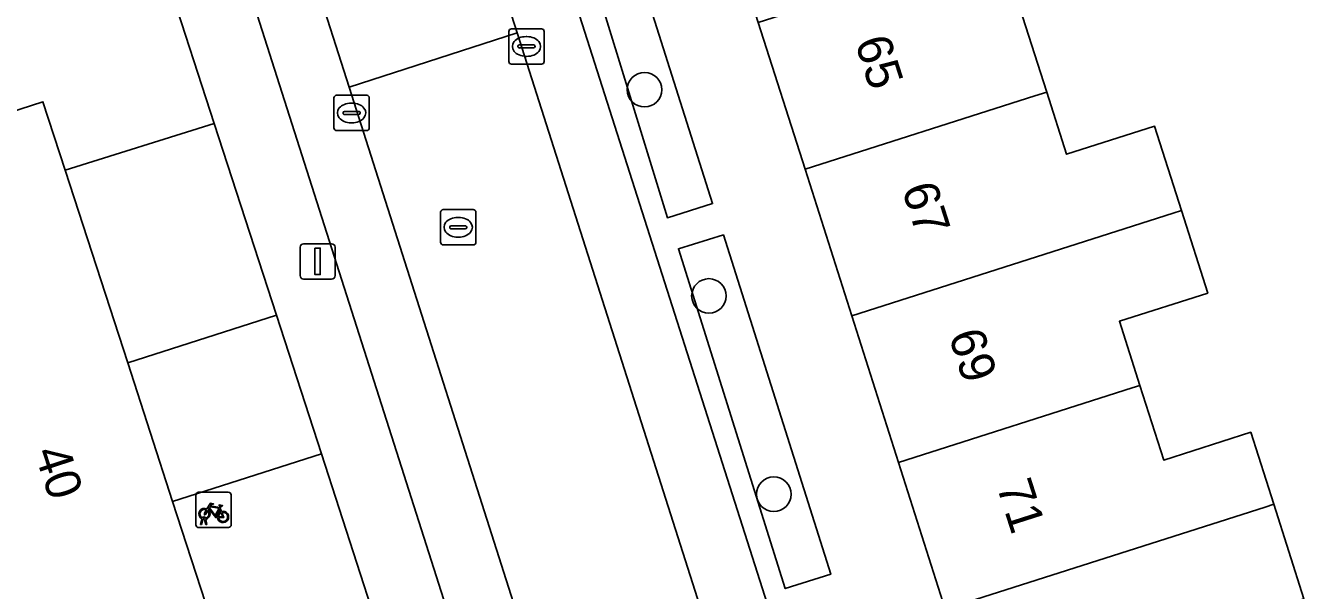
# Model space of a CAD drawing. Extents: x 159716 to 160783, y 383290 to 384031.
# Drawn here: x 160170.4 to 160206.79, y 383519.22 to 383535.21 of the extents above; entities that cross this region are included whole.
import ezdxf

# ---------------------------------------------------------------- set-up
doc = ezdxf.new("R2010")
doc.units = 0
for name, color, linetype in [('IMGEO_Boom', 7, 'Continuous'), ('IMGEO_Erf', 7, 'Continuous'), ('IMGEO_Fietsenrek', 7, 'Continuous'), ('IMGEO_Groenvoorziening', 7, 'Continuous'), ('IMGEO_Kolk', 7, 'Continuous'), ('IMGEO_Lichtmast', 7, 'Continuous'), ('IMGEO_Pand', 7, 'Continuous'), ('IMGEO_Pand_nummerreeks', 7, 'Continuous'), ('IMGEO_Parkeervlak_open', 7, 'Continuous'), ('IMGEO_Rijbaan_lokaal_open', 7, 'Continuous'), ('IMGEO_Rioolput', 7, 'Continuous'), ('IMGEO_Voetpad_open', 7, 'Continuous')]:
    doc.layers.add(name, color=color, linetype=linetype)

msp = doc.modelspace()

# ---------------------------------------------------------------- linework, layer by layer
at = {"layer": 'IMGEO_Boom'}
for centre in [(160187.928, 383533.395), (160189.752, 383527.554), (160191.59, 383521.938)]:
    msp.add_circle(centre, 0.489, dxfattribs=at)
at = {"layer": 'IMGEO_Erf'}
msp.add_lwpolyline([(160198.635, 383535.471), (160199.32, 383533.328), (160199.883, 383531.565), (160202.374, 383532.36), (160203.137, 383529.971), (160203.883, 383527.636), (160201.381, 383526.837), (160201.961, 383525.019), (160202.636, 383522.906), (160205.101, 383523.693), (160205.752, 383521.653), (160206.607, 383518.975)], dxfattribs=at)
at = {"layer": 'IMGEO_Fietsenrek'}
for p, q in [((160175.222, 383521.069), (160175.222, 383521.91)), ((160175.222, 383521.91), (160175.222, 383521.069)), ((160175.297, 383521.994), (160176.138, 383521.994)), ((160176.138, 383521.994), (160175.297, 383521.994)), ((160176.222, 383521.919), (160176.222, 383521.078)), ((160176.222, 383521.078), (160176.222, 383521.919)), ((160175.909, 383521.543), (160175.945, 383521.448)), ((160175.349, 383521.078), (160175.388, 383521.238)), ((160175.418, 383521.226), (160175.383, 383521.078)), ((160175.46, 383521.25), (160175.459, 383521.254)), ((160175.501, 383521.078), (160175.467, 383521.22)), ((160175.491, 383521.261), (160175.492, 383521.254)), ((160175.499, 383521.224), (160175.534, 383521.078)), ((160176.147, 383520.994), (160175.306, 383520.994)), ((160175.306, 383520.994), (160176.147, 383520.994)), ((160175.383, 383521.078), (160175.349, 383521.078)), ((160175.534, 383521.078), (160175.501, 383521.078))]:
    msp.add_line(p, q, dxfattribs=at)
for points in [[(160175.535, 383521.52), (160175.63, 383521.684), (160175.716, 383521.67), (160175.718, 383521.661), (160175.662, 383521.65), (160175.635, 383521.605), (160175.891, 383521.564)], [(160175.878, 383521.539), (160175.621, 383521.58), (160175.604, 383521.551), (160175.771, 383521.331), (160175.878, 383521.539)], [(160175.891, 383521.564), (160175.916, 383521.613), (160175.91, 383521.617), (160175.887, 383521.621), (160175.875, 383521.628), (160175.874, 383521.631), (160175.876, 383521.636), (160175.971, 383521.621), (160175.973, 383521.611), (160175.963, 383521.598), (160175.951, 383521.592), (160175.937, 383521.598), (160175.909, 383521.543)], [(160175.556, 383521.468), (160175.504, 383521.378), (160175.464, 383521.353), (160175.465, 383521.4), (160175.52, 383521.494)], [(160175.831, 383521.276), (160175.781, 383521.276), (160175.59, 383521.527), (160175.571, 383521.495)], [(160175.926, 383521.441), (160175.896, 383521.518), (160175.787, 383521.3), (160175.83, 383521.3)], [(160175.86, 383521.3), (160175.98, 383521.299), (160175.936, 383521.413)], [(160175.956, 383521.42), (160176.011, 383521.275), (160175.861, 383521.275)]]:
    msp.add_lwpolyline(points, dxfattribs=at)
for centre, radius, start, end in [((160175.3, 383521.916), 0.0779, 92.4484, 184.2845), ((160175.3, 383521.916), 0.0779, 92.4484, 184.2845), ((160176.144, 383521.916), 0.0779, 2.4484, 94.2845), ((160176.144, 383521.916), 0.0779, 2.4484, 94.2845), ((160175.462, 383521.379), 0.159, 62.6766, 242.1369), ((160175.462, 383521.379), 0.129, 63.3192, 238.903), ((160175.442, 383521.25), 0.0499, 12.8025, 158.6934), ((160175.462, 383521.379), 0.159, 253.9967, 271.7867), ((160175.442, 383521.25), 0.0174, 12.8025, 163.4502), ((160175.462, 383521.379), 0.129, 253.415, 269.0204), ((160175.462, 383521.379), 0.129, 283.6043, 43.4302), ((160175.462, 383521.379), 0.159, 283.5766, 46.6042), ((160175.989, 383521.295), 0.159, 113.3408, 178.3217), ((160175.989, 383521.295), 0.159, 187.0065, 105.7708), ((160175.989, 383521.295), 0.129, 113.923, 177.9556), ((160175.989, 383521.295), 0.129, 188.6715, 104.5883), ((160175.3, 383521.072), 0.0779, 182.4484, 274.2845), ((160175.3, 383521.072), 0.0779, 182.4484, 274.2845), ((160176.144, 383521.072), 0.0779, 272.4484, 4.2845), ((160176.144, 383521.072), 0.0779, 272.4484, 4.2845)]:
    msp.add_arc(centre, radius, start, end, dxfattribs=at)
at = {"layer": 'IMGEO_Groenvoorziening'}
for points in [[(160186.825, 383539.745), (160185.621, 383539.378), (160188.578, 383529.766), (160189.857, 383530.17)], [(160190.164, 383529.282), (160188.887, 383528.888), (160191.916, 383519.265), (160193.203, 383519.673)]]:
    msp.add_lwpolyline(points, close=True, dxfattribs=at)
at = {"layer": 'IMGEO_Kolk'}
for p, q in [((160184.084, 383534.193), (160184.084, 383535.045)), ((160184.159, 383535.119), (160185.011, 383535.119)), ((160185.085, 383535.045), (160185.085, 383534.193)), ((160184.386, 383534.662), (160184.784, 383534.662)), ((160184.572, 383534.899), (160184.597, 383534.899)), ((160184.343, 383534.613), (160184.343, 383534.625)), ((160184.781, 383534.576), (160184.383, 383534.576)), ((160184.595, 383534.339), (160184.57, 383534.339)), ((160184.827, 383534.625), (160184.827, 383534.613)), ((160185.011, 383534.119), (160184.159, 383534.119)), ((160179.206, 383533.237), (160180.058, 383533.237)), ((160179.131, 383532.311), (160179.131, 383533.163)), ((160179.619, 383533.017), (160179.644, 383533.017)), ((160180.132, 383533.163), (160180.132, 383532.311)), ((160179.39, 383532.731), (160179.39, 383532.743)), ((160179.828, 383532.694), (160179.43, 383532.694)), ((160179.433, 383532.78), (160179.831, 383532.78)), ((160179.642, 383532.457), (160179.617, 383532.457)), ((160179.874, 383532.743), (160179.874, 383532.731)), ((160180.058, 383532.237), (160179.206, 383532.237))]:
    msp.add_line(p, q, dxfattribs=at)
for points in [[(160184.084, 383534.193), (160184.084, 383535.045)], [(160184.159, 383535.119), (160185.011, 383535.119)], [(160185.085, 383535.045), (160185.085, 383534.193)], [(160185.011, 383534.119), (160184.159, 383534.119)], [(160179.206, 383533.237), (160180.058, 383533.237)], [(160179.131, 383532.311), (160179.131, 383533.163)], [(160180.132, 383533.163), (160180.132, 383532.311)], [(160180.058, 383532.237), (160179.206, 383532.237)]]:
    msp.add_lwpolyline(points, dxfattribs=at)
for centre, radius, start, end in [((160184.161, 383535.043), 0.0765, 91.552, 178.448), ((160184.161, 383535.043), 0.0765, 91.552, 178.448), ((160185.009, 383535.043), 0.0765, 1.552, 88.448), ((160185.009, 383535.043), 0.0765, 1.552, 88.448), ((160184.383, 383534.622), 0.0403, 85.8775, 175.7526), ((160184.788, 383534.624), 0.0386, 1.7309, 96.639), ((160184.38, 383534.612), 0.0366, 178.938, 274.7102), ((160184.784, 383534.619), 0.043, 264.8664, 352.4533), ((160184.161, 383534.195), 0.0765, 181.552, 268.448), ((160184.161, 383534.195), 0.0765, 181.552, 268.448), ((160185.009, 383534.195), 0.0765, 271.552, 358.448), ((160185.009, 383534.195), 0.0765, 271.552, 358.448), ((160179.208, 383533.161), 0.0765, 91.552, 178.448), ((160179.208, 383533.161), 0.0765, 91.552, 178.448), ((160180.056, 383533.161), 0.0765, 1.552, 88.448), ((160180.056, 383533.161), 0.0765, 1.552, 88.448), ((160179.43, 383532.74), 0.0403, 85.8775, 175.7526), ((160179.427, 383532.73), 0.0366, 178.938, 274.7102), ((160179.831, 383532.737), 0.043, 264.8664, 352.4533), ((160179.835, 383532.742), 0.0386, 1.7309, 96.639), ((160179.208, 383532.313), 0.0765, 181.552, 268.448), ((160179.208, 383532.313), 0.0765, 181.552, 268.448), ((160180.056, 383532.313), 0.0765, 271.552, 358.448), ((160180.056, 383532.313), 0.0765, 271.552, 358.448)]:
    msp.add_arc(centre, radius, start, end, dxfattribs=at)
for centre, major_axis, ratio, start_param, end_param in [((160184.571, 383534.619), (-0.387, 0.002), 0.722429, 4.712389, 7.853982), ((160184.596, 383534.619), (-0.39, 0.002), 0.717154, 1.570796, 4.712389), ((160179.618, 383532.737), (-0.387, 0.002), 0.722429, 4.712389, 7.853982), ((160179.643, 383532.737), (-0.39, 0.002), 0.717154, 1.570796, 4.712389)]:
    msp.add_ellipse(centre, major_axis=major_axis, ratio=ratio, start_param=start_param, end_param=end_param, dxfattribs=at)
at = {"layer": 'IMGEO_Lichtmast'}
for p, q in [((160178.172, 383528.132), (160178.172, 383528.932)), ((160178.172, 383528.932), (160178.172, 383528.132)), ((160178.272, 383529.032), (160179.062, 383529.032)), ((160179.062, 383529.032), (160178.272, 383529.032)), ((160179.162, 383528.932), (160179.162, 383528.132)), ((160179.162, 383528.132), (160179.162, 383528.932)), ((160179.062, 383528.032), (160178.272, 383528.032)), ((160178.272, 383528.032), (160179.062, 383528.032))]:
    msp.add_line(p, q, dxfattribs=at)
msp.add_lwpolyline([(160178.592, 383528.907), (160178.742, 383528.907), (160178.742, 383528.157), (160178.592, 383528.157), (160178.592, 383528.907)], dxfattribs=at)
for centre, start, end in [((160178.272, 383528.932), 90, 180), ((160178.272, 383528.932), 90, 180), ((160179.062, 383528.932), 0, 90), ((160179.062, 383528.932), 360, 90), ((160178.272, 383528.132), 180, 270), ((160178.272, 383528.132), 180, 270), ((160179.062, 383528.132), 270, 0), ((160179.062, 383528.132), 270, 0)]:
    msp.add_arc(centre, 0.1, start, end, dxfattribs=at)
at = {"layer": 'IMGEO_Pand'}
for points in [[(160198.635, 383535.471), (160201.054, 383536.243), (160200.412, 383538.253), (160200.241, 383538.198), (160191.149, 383535.295), (160192.474, 383531.142), (160198.986, 383533.221), (160199.32, 383533.328)], [(160202.374, 383532.36), (160199.883, 383531.565), (160199.32, 383533.328), (160198.986, 383533.221), (160192.474, 383531.142), (160193.799, 383526.989), (160202.897, 383529.894), (160203.137, 383529.971)], [(160174.562, 383521.735), (160173.289, 383525.659), (160171.518, 383531.116), (160170.889, 383533.055), (160151.395, 383526.752), (160155.574, 383513.885), (160158.009, 383506.387), (160164.625, 383508.535), (160177.491, 383512.712)], [(160201.381, 383526.837), (160203.883, 383527.636), (160203.137, 383529.971), (160202.897, 383529.894), (160193.799, 383526.989), (160195.124, 383522.836), (160201.74, 383524.948), (160201.961, 383525.019)], [(160205.101, 383523.693), (160202.636, 383522.906), (160201.961, 383525.019), (160201.74, 383524.948), (160195.124, 383522.836), (160196.448, 383518.683), (160205.503, 383521.573), (160205.752, 383521.653)], [(160204.116, 383518.179), (160206.607, 383518.975), (160205.752, 383521.653), (160205.503, 383521.573), (160196.448, 383518.683), (160197.773, 383514.529), (160204.297, 383516.612), (160204.587, 383516.705)]]:
    msp.add_lwpolyline(points, close=True, dxfattribs=at)
at = {"layer": 'IMGEO_Parkeervlak_open'}
for points in [[(160179.566, 383533.468), (160178.573, 383536.574), (160172.534, 383555.401)], [(160171.032, 383554.077), (160194.15, 383481.64), (160194.475, 383480.623)], [(160179.499, 383550.191), (160183.339, 383538.075), (160184.32, 383535.005), (160201.568, 383480.906)], [(160203.107, 383482.164), (160181.483, 383549.94)], [(160196.465, 383480.441), (160179.566, 383533.468)]]:
    msp.add_lwpolyline(points, dxfattribs=at)
at = {"layer": 'IMGEO_Rijbaan_lokaal_open'}
for points in [[(160178.573, 383536.574), (160179.566, 383533.468), (160184.32, 383535.005), (160183.339, 383538.075)], [(160184.32, 383535.005), (160179.566, 383533.468), (160196.465, 383480.441), (160201.568, 383480.906)]]:
    msp.add_lwpolyline(points, close=True, dxfattribs=at)
at = {"layer": 'IMGEO_Rioolput'}
for p, q in [((160182.151, 383529.073), (160182.151, 383529.925)), ((160182.226, 383529.999), (160183.078, 383529.999)), ((160183.152, 383529.925), (160183.152, 383529.073)), ((160182.639, 383529.779), (160182.664, 383529.779)), ((160182.41, 383529.493), (160182.41, 383529.505)), ((160182.848, 383529.456), (160182.45, 383529.456)), ((160182.453, 383529.542), (160182.851, 383529.542)), ((160182.662, 383529.219), (160182.637, 383529.219)), ((160182.894, 383529.505), (160182.894, 383529.493)), ((160183.078, 383528.999), (160182.226, 383528.999))]:
    msp.add_line(p, q, dxfattribs=at)
for points in [[(160182.151, 383529.073), (160182.151, 383529.925)], [(160182.226, 383529.999), (160183.078, 383529.999)], [(160183.152, 383529.925), (160183.152, 383529.073)], [(160183.078, 383528.999), (160182.226, 383528.999)]]:
    msp.add_lwpolyline(points, dxfattribs=at)
for centre, radius, start, end in [((160182.228, 383529.923), 0.0765, 91.552, 178.448), ((160182.228, 383529.923), 0.0765, 91.552, 178.448), ((160183.076, 383529.923), 0.0765, 1.552, 88.448), ((160183.076, 383529.923), 0.0765, 1.552, 88.448), ((160182.45, 383529.502), 0.0403, 85.8775, 175.7526), ((160182.447, 383529.492), 0.0366, 178.938, 274.7102), ((160182.851, 383529.499), 0.043, 264.8664, 352.4533), ((160182.855, 383529.504), 0.0386, 1.7309, 96.639), ((160182.228, 383529.075), 0.0765, 181.552, 268.448), ((160182.228, 383529.075), 0.0765, 181.552, 268.448), ((160183.076, 383529.075), 0.0765, 271.552, 358.448), ((160183.076, 383529.075), 0.0765, 271.552, 358.448)]:
    msp.add_arc(centre, radius, start, end, dxfattribs=at)
for centre, major_axis, ratio, start_param, end_param in [((160182.638, 383529.499), (-0.387, 0.002), 0.722429, 4.712389, 7.853982), ((160182.663, 383529.499), (-0.39, 0.002), 0.717154, 1.570796, 4.712389)]:
    msp.add_ellipse(centre, major_axis=major_axis, ratio=ratio, start_param=start_param, end_param=end_param, dxfattribs=at)
at = {"layer": 'IMGEO_Voetpad_open'}
for points in [[(160160.336, 383580.121), (160161.35, 383577.371), (160162.354, 383574.228), (160164.776, 383566.651), (160166.518, 383561.089), (160167.468, 383558.032), (160168.19, 383555.732), (160168.33, 383555.3), (160173.752, 383538.576), (160174.143, 383537.369), (160174.465, 383536.377), (160175.743, 383532.434), (160177.501, 383527.01), (160178.776, 383523.078), (160181.283, 383515.345)], [(160193.799, 383526.989), (160192.474, 383531.142), (160191.149, 383535.295), (160189.824, 383539.449), (160188.499, 383543.602), (160187.174, 383547.755), (160187.053, 383548.136), (160186.437, 383547.934), (160185.206, 383551.786), (160186.558, 383552.219), (160185.988, 383554.056), (160183.659, 383557.645)], [(160194.15, 383481.64), (160171.032, 383554.077)], [(160181.483, 383549.94), (160203.107, 383482.164)], [(160151.395, 383526.752), (160170.889, 383533.055), (160171.518, 383531.116), (160175.743, 383532.434), (160174.465, 383536.377), (160174.179, 383536.285), (160173.857, 383537.279), (160173.466, 383538.485), (160173.341, 383538.445), (160169.528, 383537.237)], [(160202.829, 383481.608), (160203.836, 383481.795), (160202.206, 383486.951), (160203.528, 383487.348), (160205.175, 383482.215), (160207.197, 383482.766), (160207.309, 383482.802), (160203.111, 383495.995), (160199.868, 383505.763), (160198.652, 383509.603), (160199.281, 383509.803), (160199.098, 383510.376), (160197.773, 383514.529), (160196.448, 383518.683), (160195.124, 383522.836), (160193.799, 383526.989)]]:
    msp.add_lwpolyline(points, dxfattribs=at)
for points in [[(160188.578, 383529.766), (160185.621, 383539.378), (160186.825, 383539.745), (160189.857, 383530.17)], [(160175.743, 383532.434), (160171.518, 383531.116), (160173.289, 383525.659), (160177.501, 383527.01)], [(160193.203, 383519.673), (160191.916, 383519.265), (160188.887, 383528.888), (160190.164, 383529.282)], [(160177.501, 383527.01), (160173.289, 383525.659), (160174.562, 383521.735), (160178.776, 383523.078)], [(160178.776, 383523.078), (160174.562, 383521.735), (160177.491, 383512.712), (160180.277, 383513.666), (160181.448, 383514.056), (160181.677, 383514.129), (160181.283, 383515.345)]]:
    msp.add_lwpolyline(points, close=True, dxfattribs=at)

# ---------------------------------------------------------------- texts
at = {"layer": 'IMGEO_Pand_nummerreeks'}
for s, rotation, p in [('65', 287.7099, (160193.88, 383534.747)), ('67', 287.7099, (160195.206, 383530.594)), ('69', 287.7099, (160196.532, 383526.441)), ('40', 287.9907, (160170.638, 383523.127)), ('71', 287.7099, (160197.892, 383522.18))]:
    msp.add_text(s, height=1, rotation=rotation, dxfattribs=at).set_placement(p)

doc.saveas('drawing.dxf')
